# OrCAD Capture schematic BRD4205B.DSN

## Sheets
1 03: I/O Port Connections: size A3; title: ZGM230S Radio Board; rev: A00; company: Silicon Labs; note: BRD4205B; note: TAB; note: JSH
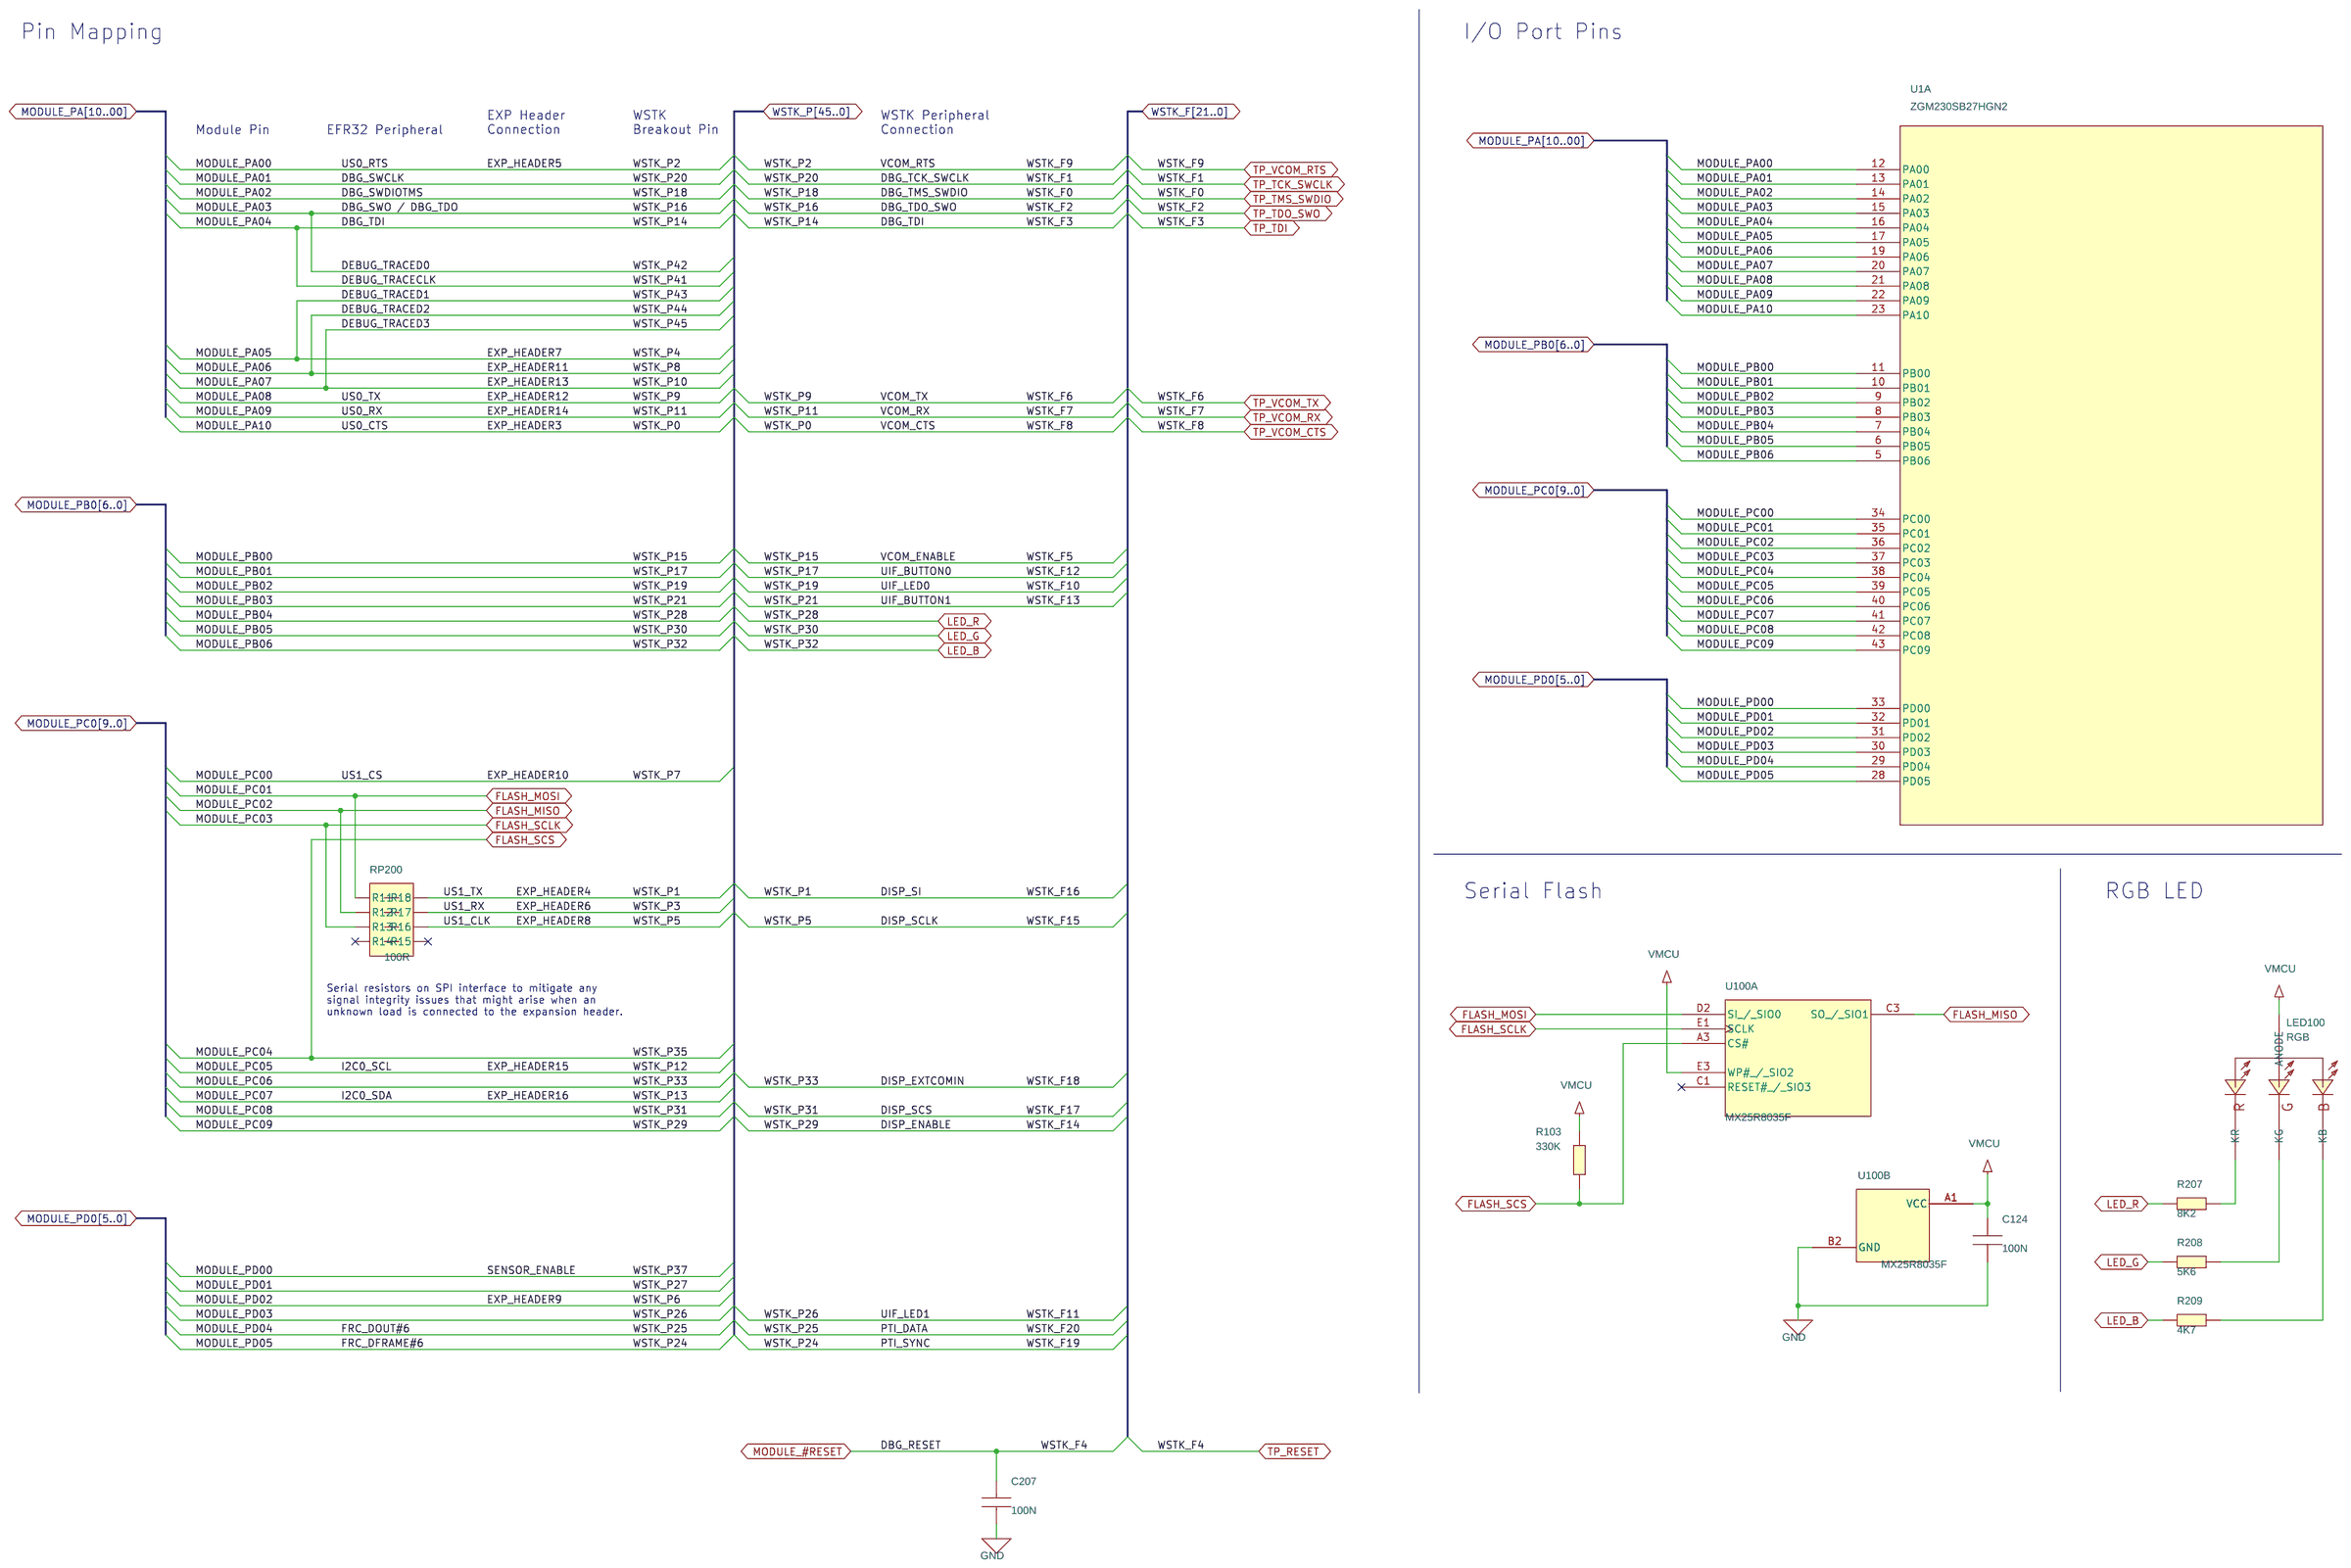
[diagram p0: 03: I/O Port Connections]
2 01: Title Page
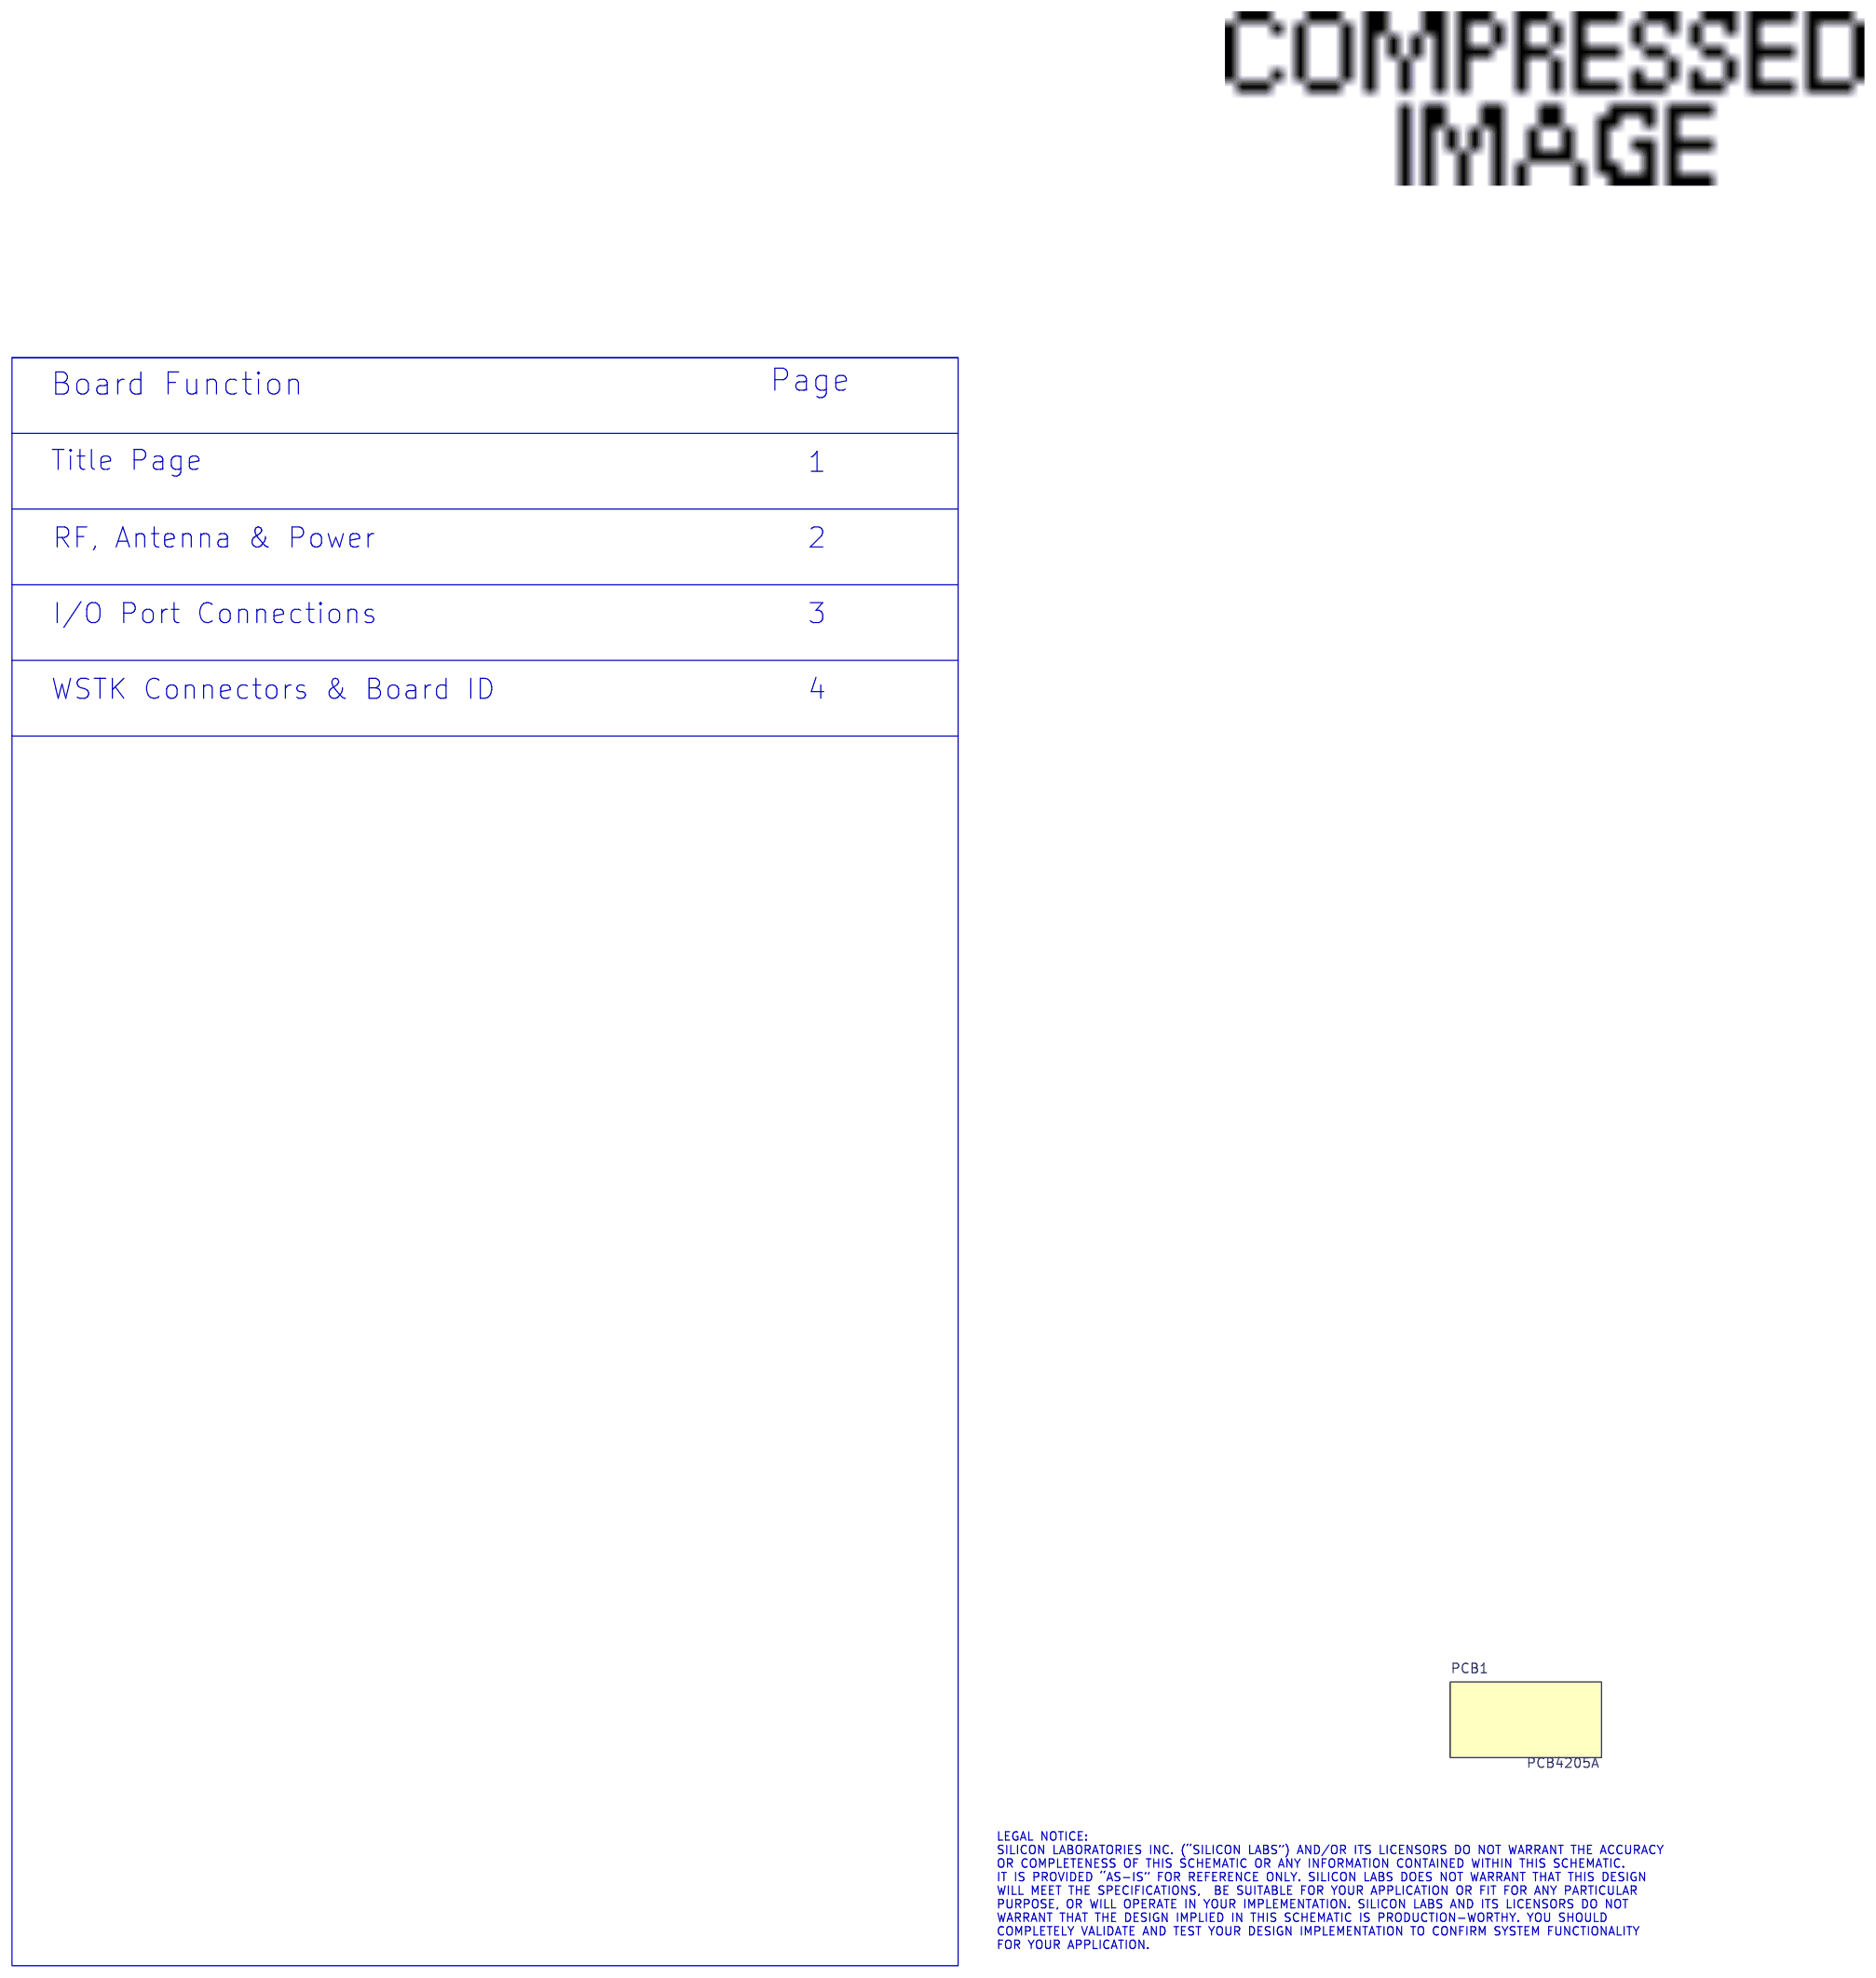
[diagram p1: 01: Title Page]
3 02: RF, Antenna and Power: size A3
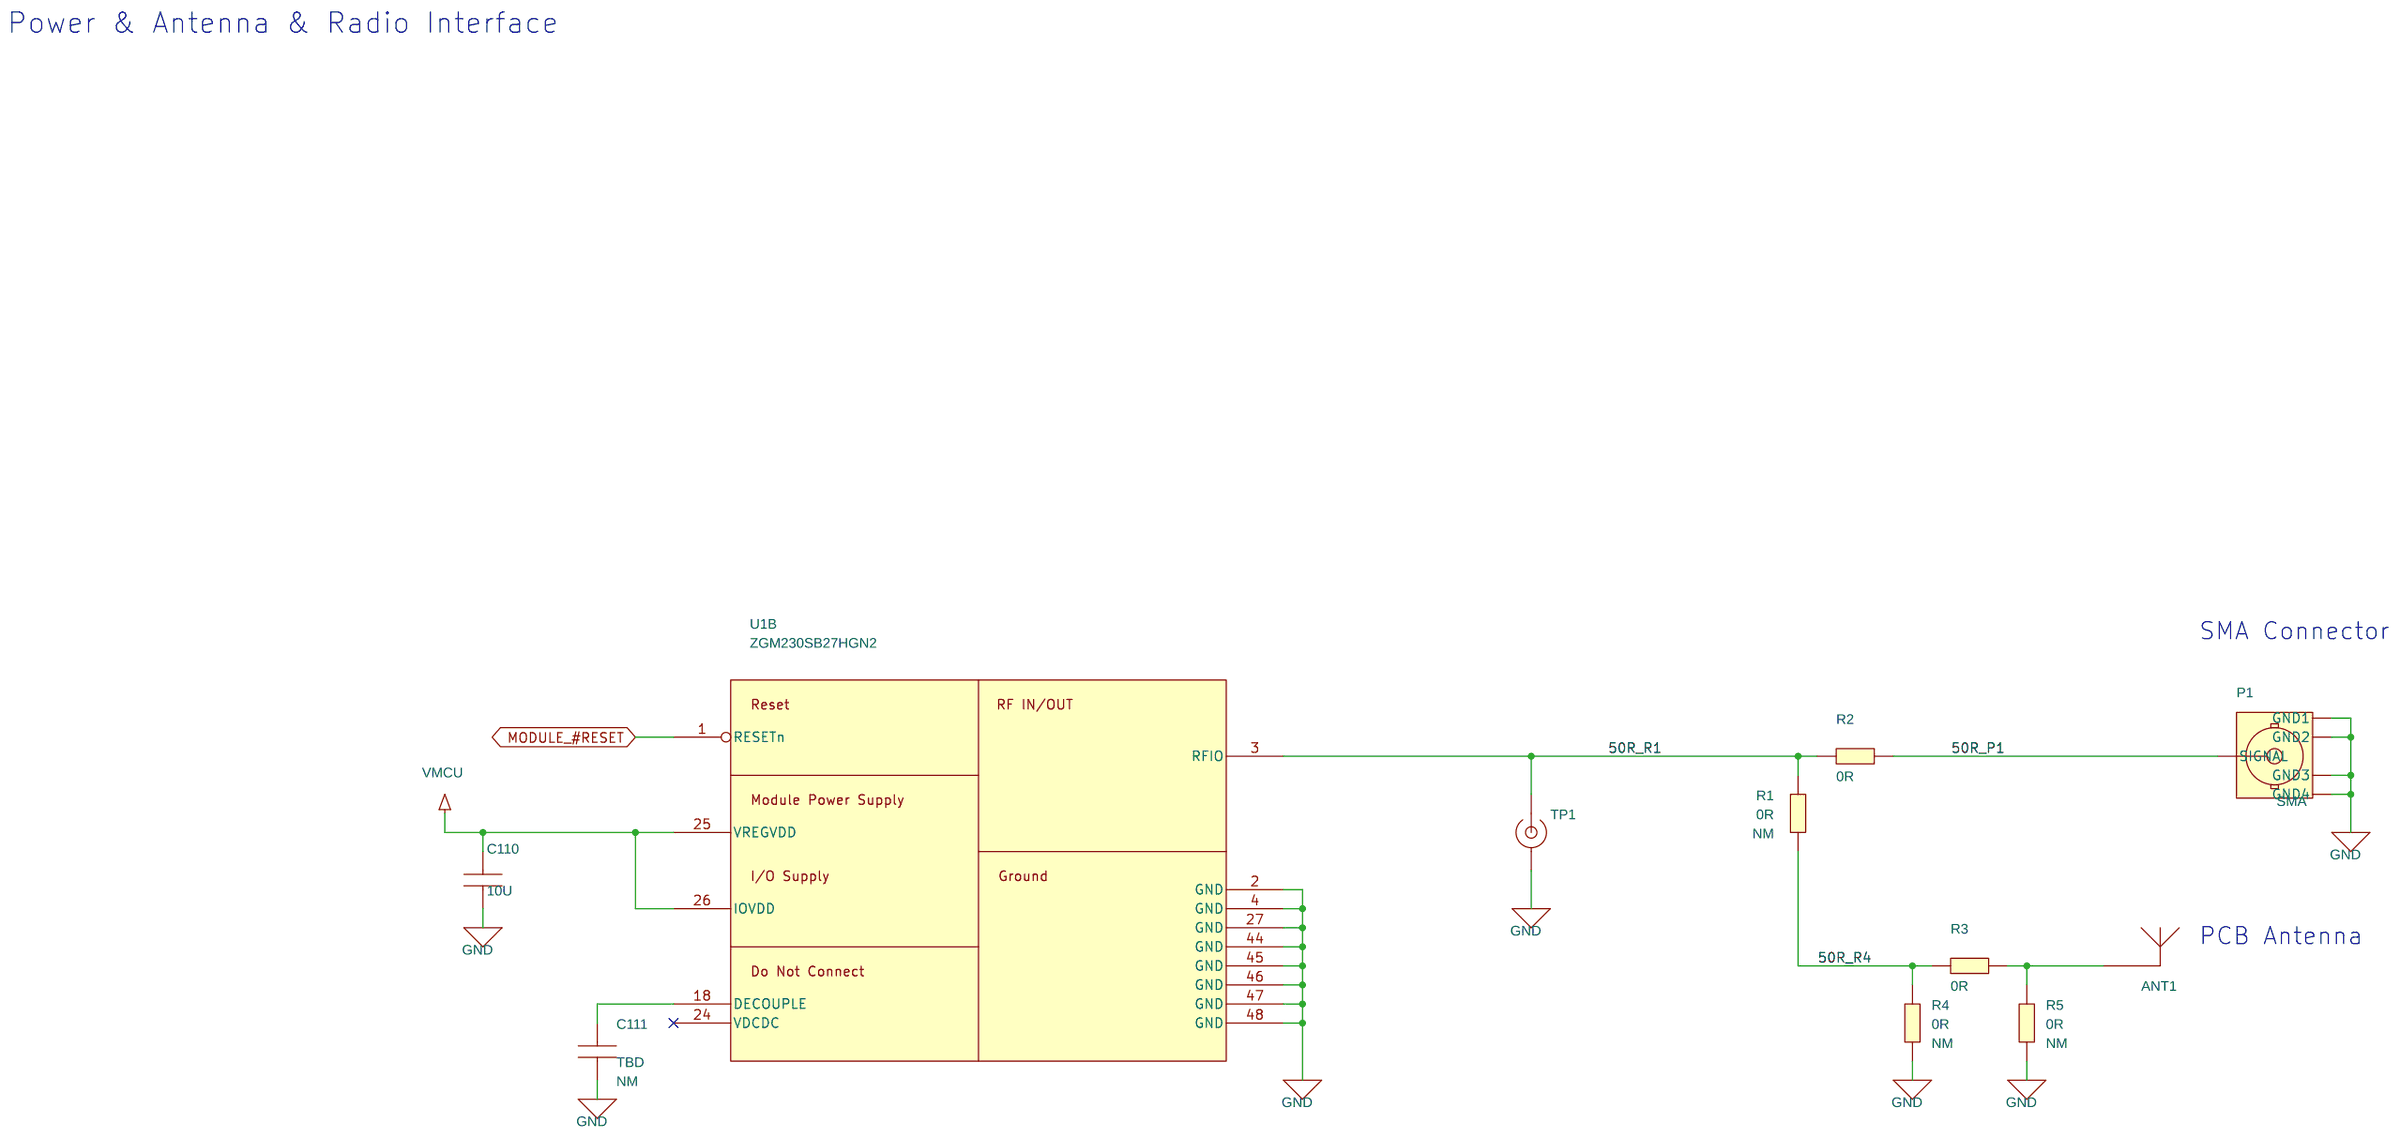
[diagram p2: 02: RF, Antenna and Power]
4 04: WSTK Connectors & Board ID: size A3
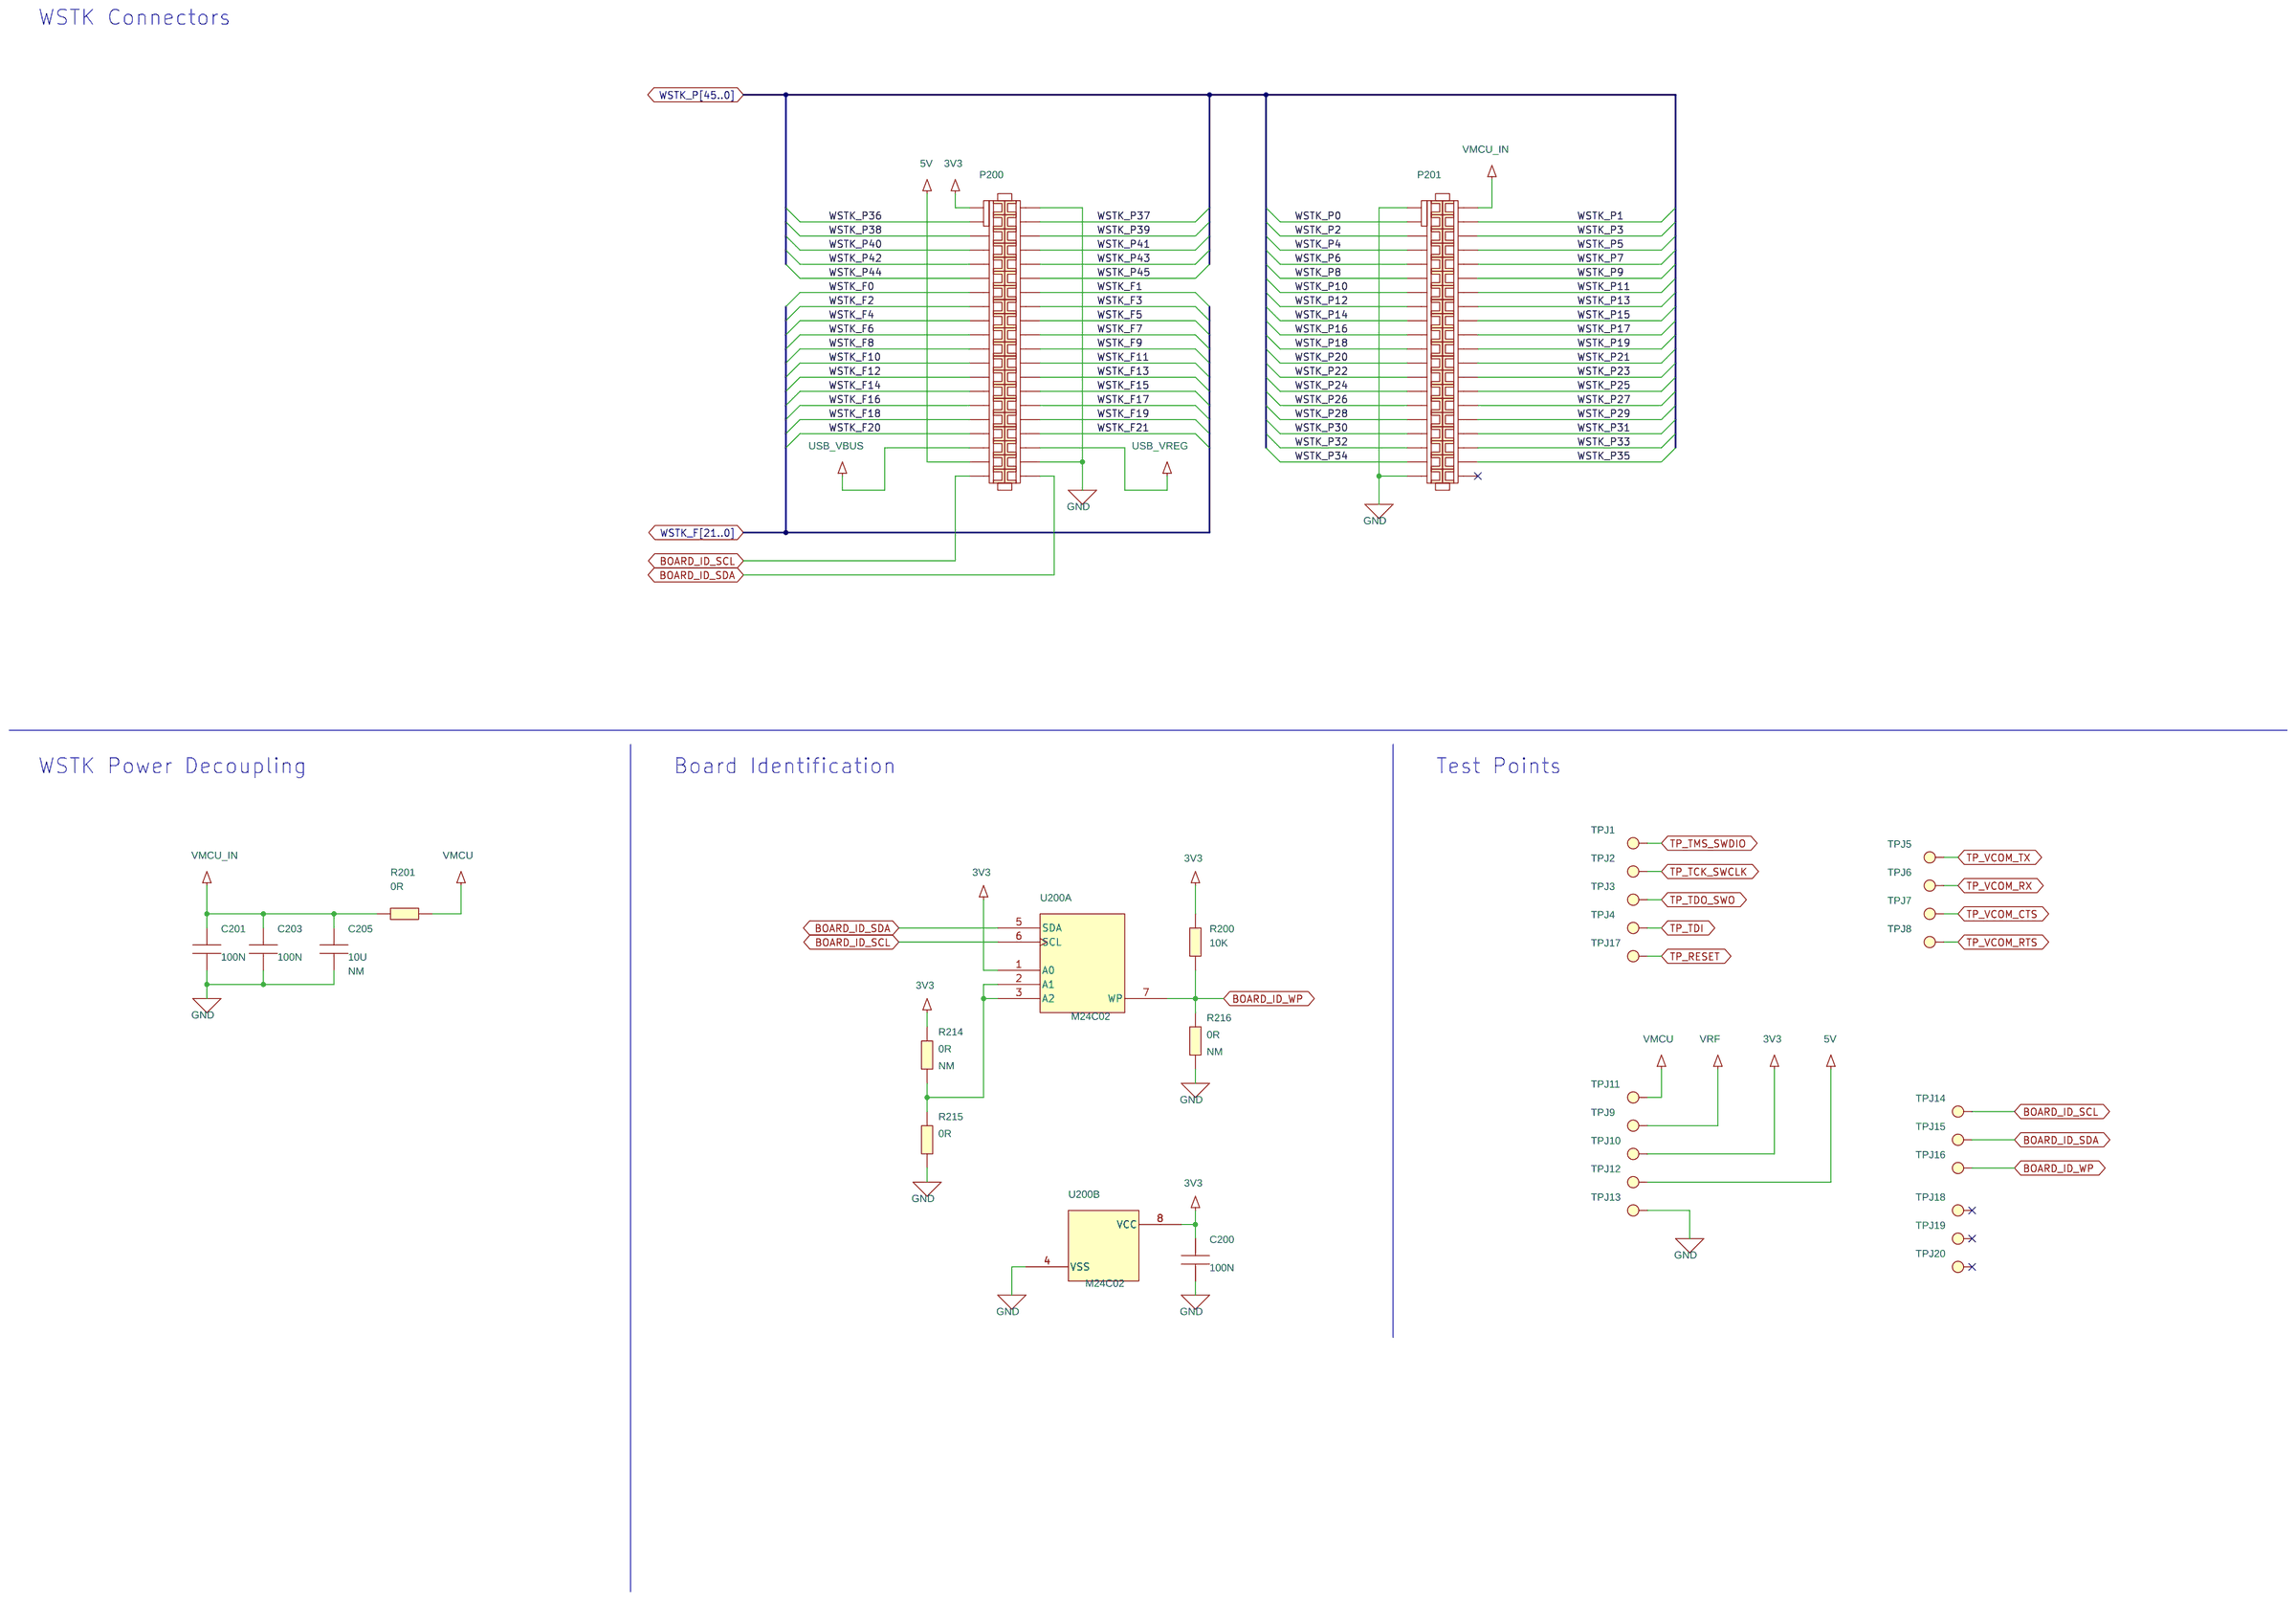
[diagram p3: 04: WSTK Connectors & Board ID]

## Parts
sheet 01: Title Page
PCB1  PCB4205A  [N/A]
sheet 02: RF, Antenna and Power
ANT1  Antenna  [ANT_PRINTED_x]
C110  10U  [C0603_L]
C111  TBD  [C0402_L]
P1  SMA  [TE_SMA_1814832_TH_VER]
R1  0R  [R0201_L]
R2  0R  [R0201_L]
R3  0R  [R0201_L]
R4  0R  [R0201_L]
R5  0R  [R0201_L]
TP1  TP_RF  [TP_INGUN_50_OHM_CLOSED openvia]
sheet 03: I/O Port Connections
C124  100N  [C0201_L]
C207  100N  [C0201_L]
LED100  RGB  [LED_LUMEX_SML_LX0404]
R103  330K  [R0201_L]
R207  8K2  [R0402_L]
R208  5K6  [R0402_L]
R209  4K7  [R0402_L]
RP200  100R  [RES_MNR04-8]
U1  ZGM230SB27HGN2  [ZGM230S]  (sections A,B)
U100  MX25R8035F  [BGA8_M040_1.24x1.75_WLCSP]  (sections A,B)
sheet 04: WSTK Connectors & Board ID
C200  100N  [C0201_L]
C201  100N  [C0201_L]
C203  100N  [C0201_L]
C205  10U  [C0805_L]
P200  SOCKET_WCON_2X20_1.27MM_SMD  [SAM_SFC-120-T2-D-A-2X20_SNUM]
P201  SOCKET_WCON_2X20_1.27MM_SMD  [SAM_SFC-120-T2-D-A-2X20_SNUM]
R200  10K  [R0402_L]
R201  0R  [R0402_L]
R214  0R  [R0402_L]
R215  0R  [R0402_L]
R216  0R  [R0402_L]
TPJ1  TPJ_SMD  [TP_1.0_SMD]
TPJ2  TPJ_SMD  [TP_1.0_SMD]
TPJ3  TPJ_SMD  [TP_1.0_SMD]
TPJ4  TPJ_SMD  [TP_1.0_SMD]
TPJ5  TPJ_SMD  [TP_1.0_SMD]
TPJ6  TPJ_SMD  [TP_1.0_SMD]
TPJ7  TPJ_SMD  [TP_1.0_SMD]
TPJ8  TPJ_SMD  [TP_1.0_SMD]
TPJ9  TPJ_SMD  [TP_1.0_SMD]
TPJ10  TPJ_SMD  [TP_1.0_SMD]
TPJ11  TPJ_SMD  [TP_1.0_SMD]
TPJ12  TPJ_SMD  [TP_1.0_SMD]
TPJ13  TPJ_SMD  [TP_1.0_SMD]
TPJ14  TPJ_SMD  [TP_1.0_SMD]
TPJ15  TPJ_SMD  [TP_1.0_SMD]
TPJ16  TPJ_SMD  [TP_1.0_SMD]
TPJ17  TPJ_SMD  [TP_1.0_SMD]
TPJ18  TPJ_SMD  [TP_1.0_SMD]
TPJ19  TPJ_SMD  [TP_1.0_SMD]
TPJ20  TPJ_SMD  [TP_1.0_SMD]
U200  M24C02  [8-TDFN]  (sections A,B)

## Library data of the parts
PCB1 = PCB: Mfg #: PCB4205A Rev. A00; Price_1K: 1.25
ANT1 = ANT_Z-WAVE_WB
C110 = C0603: Rating: 6.3V; Technology: X5R; Tolerance: 20%
C111 = C0402: Not Mounted: NM; Rating: 6.3V; Technology: X7R; Tolerance: 10%
P1 = SMA_TH_WELLSHOW
R1 R4 R5 = R0201: Not Mounted: NM
R2 R3 R103 = R0201
TP1 = TP_RF
C124 = C0201: Rating: 25V; Technology: X5R; Tolerance: 10%
C200 C201 C203 C207 = C0201: Rating: 16V; Technology: X7S; Tolerance: 20%
LED100 = LED3_COMMON_ANODE_0: Mfg: Lumex; Mfg #: LX0404SIUPGUSB; Price_1K: 0.35
R207-R209 = R0402: Rating: 63mW; Tolerance: 1%
RP200 = MNR04M0APJ101
U1 = ZGM230S: Mfg #: ZGM230SB27HGN2R
U100 = MX25R8035
C205 = CAPACITOR: Not Mounted: NM; Technology: X5R
P200 P201 = SOCKET_WCON_2X20_1.27MM_SMD: Mfg #: 2344-220MS3CUNR6
R200 R215 = R0402
R201 = RESISTOR
R214 R216 = R0402: Not Mounted: NM
TPJ1-TPJ20 = TPJ_SMD
U200 = 24AA024: Mfg: ST Microelectronics; Mfg #: M24C02-FMC6TG; Price_1K: 0.26

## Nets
3V3: C200.1 P200.1 R200.2 R214.1 TPJ10.1(TP) U200.1(A0) U200.8(VCC)
5V: P200.37 TPJ12.1(TP)
GND: C110.2 C111.2 C124.2 C200.2 C201.2 C203.2 C205.2 C207.2 P1.2(GND1) P1.3(GND2) P1.4(GND3) P1.5(GND4) P200.2 P200.38 P201.1 P201.39 R4.2 R5.2 R215.2 R216.2 TP1.2(GND) TPJ13.1(TP) U1.2(GND) U1.4(GND) U1.27(GND) U1.44(GND) U1.45(GND) U1.46(GND) U1.47(GND) U1.48(GND) U100.B2(GND) U200.4(VSS)
50R_P1: P1.1(SIGNAL) R2.2
50R_R1: R1.1 R2.1 TP1.1(RF) U1.3(RFIO)
50R_R4: R1.2 R3.1 R4.1
BOARD_ID_SCL: P200.39 TPJ14.1(TP) U200.6(SCL)
BOARD_ID_SDA: P200.40 TPJ15.1(TP) U200.5(SDA)
BOARD_ID_WP: R200.1 R216.1 TPJ16.1(TP) U200.7(WP)
FLASH_MISO: RP200.2(R12) U1.36(PC02) U100.C3(SO_/_SIO1)
FLASH_MOSI: RP200.1(R11) U1.35(PC01) U100.D2(SI_/_SIO0)
FLASH_SCLK: RP200.3(R13) U1.37(PC03) U100.E1(SCLK)
FLASH_SCS: P201.38 R103.1 U1.38(PC04) U100.A3(CS#)
LED_B: P201.35 R209.1 U1.5(PB06)
LED_G: P201.33 R208.1 U1.6(PB05)
LED_R: P201.31 R207.1 U1.7(PB04)
MODULE_#RESET: C207.1 P200.17 TPJ17.1(TP) U1.1(RESETn)
MODULE_PA10: P200.21 P201.3 TPJ7.1(TP) U1.23(PA10)
MODULE_PB00: P200.18 P201.18 U1.11(PB00)
MODULE_PB01: P200.25 P201.20 U1.10(PB01)
MODULE_PB02: P200.23 P201.22 U1.9(PB02)
MODULE_PB03: P200.26 P201.24 U1.8(PB03)
MODULE_PC00: P201.10 U1.34(PC00)
MODULE_PC05: P201.15 U1.39(PC05)
MODULE_PC06: P200.31 P201.36 U1.40(PC06)
MODULE_PC07: P201.16 U1.41(PC07)
MODULE_PC08: P200.30 P201.34 U1.42(PC08)
MODULE_PC09: P200.27 P201.32 U1.43(PC09)
MODULE_PD00: P200.4 U1.33(PD00)
MODULE_PD01: P201.30 U1.32(PD01)
MODULE_PD02: P201.9 U1.31(PD02)
MODULE_PD03: P200.24 P201.29 U1.30(PD03)
MODULE_PD04: P200.33 P201.28 U1.29(PD04)
MODULE_PD05: P200.32 P201.27 U1.28(PD05)
TP_TCK_SWCLK: P200.14 P201.23 TPJ2.1(TP) U1.13(PA01)
TP_TDI: P200.8 P200.16 P201.17 TPJ4.1(TP) U1.16(PA04)
TP_TDO_SWO: P200.9 P200.15 P201.19 TPJ3.1(TP) U1.15(PA03)
TP_TMS_SWDIO: P200.13 P201.21 TPJ1.1(TP) U1.14(PA02)
TP_VCOM_RTS: P200.22 P201.5 TPJ8.1(TP) U1.12(PA00)
TP_VCOM_RX: P200.20 P201.14 TPJ6.1(TP) U1.22(PA09)
TP_VCOM_TX: P200.19 P201.12 TPJ5.1(TP) U1.21(PA08)
USB_VBUS: P200.35
USB_VREG: P200.36
VMCU: C110.1 C124.1 LED100.1(ANODE) R103.2 R201.2 TPJ11.1(TP) U1.25(VREGVDD) U1.26(IOVDD) U100.A1(VCC) U100.E3(WP#_/_SIO2)
VMCU_IN: C201.1 C203.1 C205.1 P201.2 R201.1
VRF: TPJ9.1(TP)
WSTK_F15: P200.28 P201.8 RP200.6(R16)
WSTK_F16: P200.29 P201.4 RP200.8(R18)
WSTK_F21: P200.34
WSTK_P3: P201.6 RP200.7(R17)
WSTK_P4: P200.10 P201.7 U1.17(PA05)
WSTK_P10: P200.12 P201.13 U1.20(PA07)
WSTK_P22: P201.25
WSTK_P23: P201.26
WSTK_P34: P201.37
WSTK_P36: P200.3
WSTK_P38: P200.5
WSTK_P39: P200.6
WSTK_P40: P200.7
WSTK_P44: P200.11 P201.11 U1.19(PA06)
N16816267: ANT1.1 R3.2 R5.1
N16816297: C111.1 U1.18(DECOUPLE)
N16818249: R214.2 R215.1 U200.2(A1) U200.3(A2)
N16824562: LED100.2(KR) R207.2
N16824576: LED100.3(KB) R209.2
N16824582: LED100.4(KG) R208.2

Not connected (* = marked no-connect by the designer): P201 40*; RP200 4(R14)* 5(R15)*; TPJ18 1(TP)*; TPJ19 1(TP)*; TPJ20 1(TP)*; U1 24(VDCDC)*; U100 C1(RESET#_/_SIO3)*

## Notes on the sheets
sheet 1
- Pin Mapping
- I/O Port Pins
- EXP Header
  Connection
- WSTK
  Breakout Pin
- WSTK Peripheral
  Connection
- Module Pin
- EFR32 Peripheral
- Serial Flash
- RGB LED
- Serial resistors on SPI interface to mitigate any
  signal integrity issues that might arise when an
  unknown load is connected to the expansion header.
sheet 2
- Board Function
- Page
- Title Page
- 1
- RF, Antenna & Power
- 2
- I/O Port Connections
- 3
- WSTK Connectors & Board ID
- 4
- LEGAL NOTICE:
  SILICON LABORATORIES INC. (“SILICON LABS”) AND/OR ITS LICENSORS DO NOT WARRANT THE ACCURACY
  OR COMPLETENESS OF THIS SCHEMATIC OR ANY INFORMATION CONTAINED WITHIN THIS SCHEMATIC.
  IT IS PROVIDED “AS-IS” FOR REFERENCE ONLY. SILICON LABS DOES NOT WARRANT THAT THIS DESIGN
  WILL MEET THE SPECIFICATIONS,  BE SUITABLE FOR YOUR APPLICATION OR FIT FOR ANY PARTICULAR
  PURPOSE, OR WILL OPERATE IN YOUR IMPLEMENTATION. SILICON LABS AND ITS LICENSORS DO NOT
  WARRANT THAT THE DESIGN IMPLIED IN THIS SCHEMATIC IS PRODUCTION-WORTHY. YOU SHOULD
  COMPLETELY VALIDATE AND TEST YOUR DESIGN IMPLEMENTATION TO CONFIRM SYSTEM FUNCTIONALITY
  FOR YOUR APPLICATION.
sheet 3
- Power & Antenna & Radio Interface
- SMA Connector
- PCB Antenna
sheet 4
- WSTK Connectors
- WSTK Power Decoupling
- Board Identification
- Test Points
